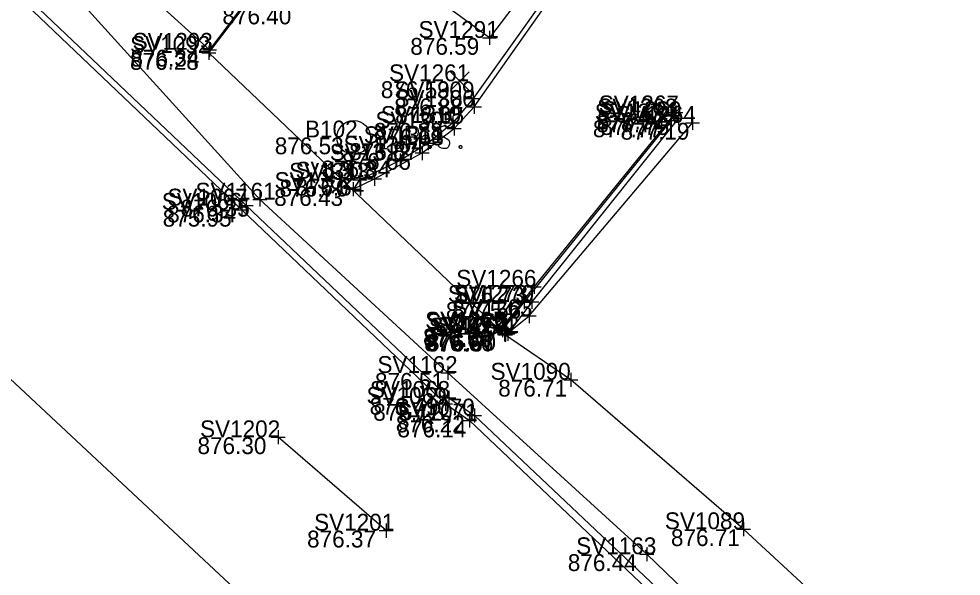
# Model space of a CAD drawing. Extents: x 1480001 to 1480402, y 379235 to 379603.
# Drawn here: x 1480268.3 to 1480335.4, y 379321.1 to 379360.8 of the extents above; entities that cross this region are included whole.
import ezdxf

# ---------------------------------------------------------------- set-up
doc = ezdxf.new("R2010")
doc.units = 0
for name, color, linetype in [('PM_P_CL_Double_Solid', 7, 'Continuous'), ('PM_X_Lane_Line', 7, 'Continuous'), ('PV_X_Curb', 7, 'Continuous'), ('PV_X_Driveway', 7, 'Continuous'), ('PV_X_Walk', 7, 'Continuous'), ('RD_X_Wall', 7, 'Continuous'), ('SV_P_Mon_Cells_Set', 7, 'Continuous'), ('SV_X_Random_Point', 7, 'Continuous'), ('SV_X_Shot_Marker', 7, 'Continuous'), ('SV_X_Text_Elevation', 7, 'Continuous'), ('SV_X_Text_Name', 7, 'Continuous'), ('UT_X_Water', 7, 'Continuous')]:
    doc.layers.add(name, color=color, linetype=linetype)

msp = doc.modelspace()

# ---------------------------------------------------------------- linework, layer by layer
at = {"layer": 'PM_P_CL_Double_Solid'}
msp.add_lwpolyline([(1480349.171, 379259.048), (1480326.954, 379280.06), (1480305.568, 379299.916), (1480284.393, 379319.578), (1480263.301, 379339.268), (1480242.575, 379359.213), (1480224.612, 379376.165), (1480208.191, 379391.527)], dxfattribs=at)
at = {"layer": 'PM_X_Lane_Line'}
msp.add_line((1480294.465, 379324.383), (1480286.766, 379331.035), dxfattribs=at)
at = {"layer": 'PV_X_Curb'}
for points in [[(1480221.495, 379406.235), (1480232.955, 379395.538), (1480249.633, 379380.044), (1480261.648, 379368.645), (1480263.97, 379366.423), (1480266.337, 379364.241), (1480284.168, 379347.237), (1480298.679, 379333.414), (1480300.396, 379332.229), (1480315.326, 379318.045), (1480323.87, 379309.98), (1480343.087, 379291.663), (1480360.248, 379275.585)], [(1480221.908, 379406.565), (1480233.156, 379396.15), (1480249.934, 379380.311), (1480262.014, 379368.886), (1480262.346, 379369.254), (1480264.513, 379367.165), (1480266.627, 379365.06), (1480266.41, 379364.736), (1480284.493, 379347.537), (1480298.919, 379333.838), (1480300.736, 379332.585), (1480315.855, 379318.308), (1480323.784, 379310.749), (1480324.548, 379310.084), (1480343.241, 379292.305), (1480360.288, 379276.242)], [(1480305.96, 379362.631), (1480300.661, 379355.172), (1480299.212, 379353.42), (1480297.448, 379351.979), (1480295.46, 379350.738), (1480292.571, 379349.379)]]:
    msp.add_lwpolyline(points, dxfattribs=at)
at = {"layer": 'PV_X_Driveway'}
for points in [[(1480292.11, 379348.712), (1480293.619, 379349.452), (1480297.028, 379351.282), (1480299.308, 379353.024), (1480300.735, 379354.566), (1480306.287, 379362.479)], [(1480302.714, 379338.771), (1480305.004, 379341.756), (1480315.073, 379354.175)], [(1480302.964, 379338.339), (1480304.645, 379339.672), (1480316.266, 379353.432)]]:
    msp.add_lwpolyline(points, dxfattribs=at)
at = {"layer": 'PV_X_Walk'}
for points in [[(1480355.123, 379297.828), (1480351.285, 379293.6), (1480334.098, 379309.328), (1480328.212, 379315.428), (1480328.737, 379316.329), (1480319.905, 379324.485), (1480307.606, 379335.13), (1480302.895, 379338.359), (1480281.823, 379358.406), (1480285.611, 379363.387), (1480280.441, 379367.109), (1480277.224, 379362.834), (1480260.819, 379378.019), (1480244.572, 379393.153), (1480235.613, 379401.335), (1480215.341, 379421.047)], [(1480304.825, 379363.469), (1480301.807, 379359.476), (1480289.404, 379368.611), (1480281.88, 379358.636), (1480277.384, 379362.714), (1480284.099, 379372.064), (1480266.845, 379384.676), (1480270.146, 379389.834)]]:
    msp.add_lwpolyline(points, dxfattribs=at)
at = {"layer": 'RD_X_Wall'}
msp.add_lwpolyline([(1480314.978, 379353.953), (1480315.27, 379353.766), (1480304.822, 379340.687), (1480303.116, 379338.406), (1480302.744, 379338.663), (1480304.288, 379340.662), (1480314.743, 379353.603)], dxfattribs=at)
at = {"layer": 'SV_P_Mon_Cells_Set'}
for points in [[(1480294.165, 379353.191), (1480294.518, 379353.191)], [(1480294.341, 379351.591), (1480294.341, 379353.191)], [(1480295.907, 379351.591), (1480295.907, 379353.191), (1480296.436, 379353.191), (1480296.491, 379353.178), (1480296.568, 379353.153), (1480296.601, 379353.128), (1480296.634, 379353.102), (1480296.678, 379353.04), (1480296.711, 379352.976), (1480296.733, 379352.876), (1480296.733, 379352.724), (1480296.722, 379352.674), (1480296.7, 379352.598), (1480296.656, 379352.51), (1480296.612, 379352.473), (1480296.579, 379352.447), (1480296.524, 379352.422), (1480296.436, 379352.41), (1480295.907, 379352.41)], [(1480298.916, 379353.077), (1480298.894, 379353.102), (1480298.861, 379353.128), (1480298.762, 379353.165), (1480298.64, 379353.191), (1480298.552, 379353.191), (1480298.519, 379353.191), (1480298.376, 379353.153), (1480298.255, 379353.077), (1480298.177, 379352.976), (1480298.155, 379352.876), (1480298.155, 379352.8), (1480298.177, 379352.699), (1480298.266, 379352.611), (1480298.872, 379352.233), (1480298.927, 379352.183), (1480298.949, 379352.132), (1480298.971, 379352.057), (1480298.971, 379351.981), (1480298.96, 379351.906), (1480298.949, 379351.855), (1480298.927, 379351.792), (1480298.905, 379351.742), (1480298.883, 379351.704), (1480298.85, 379351.666), (1480298.817, 379351.641), (1480298.773, 379351.616), (1480298.74, 379351.603), (1480298.64, 379351.591), (1480298.486, 379351.591), (1480298.387, 379351.616), (1480298.243, 379351.704), (1480298.155, 379351.78)], [(1480295.3, 379351.805), (1480295.355, 379351.805), (1480295.389, 379351.78), (1480295.422, 379351.729), (1480295.422, 379351.666), (1480295.389, 379351.616), (1480295.355, 379351.591), (1480295.3, 379351.591), (1480295.267, 379351.616), (1480295.234, 379351.666), (1480295.234, 379351.729), (1480295.267, 379351.78), (1480295.3, 379351.805)], [(1480297.549, 379351.805), (1480297.604, 379351.805), (1480297.637, 379351.78), (1480297.67, 379351.729), (1480297.67, 379351.666), (1480297.637, 379351.616), (1480297.604, 379351.591), (1480297.549, 379351.591), (1480297.516, 379351.616), (1480297.483, 379351.666), (1480297.483, 379351.729), (1480297.516, 379351.78), (1480297.549, 379351.805)], [(1480299.732, 379351.805), (1480299.787, 379351.805), (1480299.82, 379351.78), (1480299.853, 379351.729), (1480299.853, 379351.666), (1480299.82, 379351.616), (1480299.787, 379351.591), (1480299.732, 379351.591), (1480299.698, 379351.616), (1480299.666, 379351.666), (1480299.666, 379351.729), (1480299.698, 379351.78), (1480299.732, 379351.805)], [(1480294.165, 379351.591), (1480294.518, 379351.591)]]:
    msp.add_lwpolyline(points, dxfattribs=at)
msp.add_circle((1480292.146, 379352.389), 1.2, dxfattribs=at)
at = {"layer": 'SV_X_Random_Point'}
for p, q in [((1480299.039, 379355.724), (1480300.373, 379357.059)), ((1480299.039, 379357.059), (1480300.373, 379355.724))]:
    msp.add_line(p, q, dxfattribs=at)
at = {"layer": 'SV_X_Shot_Marker'}
for p, q in [((1480301.807, 379359.976), (1480301.807, 379358.976)), ((1480281.88, 379359.136), (1480281.88, 379358.136)), ((1480301.307, 379359.476), (1480302.307, 379359.476)), ((1480301.807, 379359.476), (1480301.807, 379359.476)), ((1480281.38, 379358.636), (1480282.38, 379358.636)), ((1480281.823, 379358.906), (1480281.823, 379357.906)), ((1480281.88, 379358.636), (1480281.88, 379358.636)), ((1480281.323, 379358.406), (1480282.323, 379358.406)), ((1480281.823, 379358.406), (1480281.823, 379358.406)), ((1480300.161, 379355.172), (1480301.161, 379355.172)), ((1480300.661, 379355.672), (1480300.661, 379354.672)), ((1480300.661, 379355.172), (1480300.661, 379355.172)), ((1480300.235, 379354.566), (1480301.235, 379354.566)), ((1480300.735, 379355.066), (1480300.735, 379354.066)), ((1480300.735, 379354.566), (1480300.735, 379354.566)), ((1480314.978, 379354.453), (1480314.978, 379353.453)), ((1480315.073, 379354.675), (1480315.073, 379353.675)), ((1480299.212, 379353.92), (1480299.212, 379352.92)), ((1480314.478, 379353.953), (1480315.478, 379353.953)), ((1480314.573, 379354.175), (1480315.573, 379354.175)), ((1480314.743, 379354.103), (1480314.743, 379353.103)), ((1480314.77, 379353.766), (1480315.77, 379353.766)), ((1480314.978, 379353.953), (1480314.978, 379353.953)), ((1480315.073, 379354.175), (1480315.073, 379354.175)), ((1480315.27, 379354.266), (1480315.27, 379353.266)), ((1480315.27, 379353.766), (1480315.27, 379353.766)), ((1480316.266, 379353.932), (1480316.266, 379352.932)), ((1480298.712, 379353.42), (1480299.712, 379353.42)), ((1480299.212, 379353.42), (1480299.212, 379353.42)), ((1480299.308, 379353.524), (1480299.308, 379352.524)), ((1480314.243, 379353.603), (1480315.243, 379353.603)), ((1480314.743, 379353.603), (1480314.743, 379353.603)), ((1480315.766, 379353.432), (1480316.766, 379353.432)), ((1480316.266, 379353.432), (1480316.266, 379353.432)), ((1480297.448, 379352.479), (1480297.448, 379351.479)), ((1480298.808, 379353.024), (1480299.808, 379353.024)), ((1480299.308, 379353.024), (1480299.308, 379353.024)), ((1480296.948, 379351.979), (1480297.948, 379351.979)), ((1480297.028, 379351.782), (1480297.028, 379350.782)), ((1480297.448, 379351.979), (1480297.448, 379351.979)), ((1480295.46, 379351.238), (1480295.46, 379350.238)), ((1480296.528, 379351.282), (1480297.528, 379351.282)), ((1480297.028, 379351.282), (1480297.028, 379351.282)), ((1480294.96, 379350.738), (1480295.96, 379350.738)), ((1480295.46, 379350.738), (1480295.46, 379350.738)), ((1480292.571, 379349.879), (1480292.571, 379348.879)), ((1480293.619, 379349.952), (1480293.619, 379348.952)), ((1480292.071, 379349.379), (1480293.071, 379349.379)), ((1480292.11, 379349.212), (1480292.11, 379348.212)), ((1480292.571, 379349.379), (1480292.571, 379349.379)), ((1480293.119, 379349.452), (1480294.119, 379349.452)), ((1480293.619, 379349.452), (1480293.619, 379349.452)), ((1480285.468, 379348.459), (1480285.468, 379347.459)), ((1480291.61, 379348.712), (1480292.61, 379348.712)), ((1480292.11, 379348.712), (1480292.11, 379348.712)), ((1480284.168, 379347.737), (1480284.168, 379346.737)), ((1480284.493, 379348.037), (1480284.493, 379347.037)), ((1480284.968, 379347.959), (1480285.968, 379347.959)), ((1480285.468, 379347.959), (1480285.468, 379347.959)), ((1480283.668, 379347.237), (1480284.668, 379347.237)), ((1480283.993, 379347.537), (1480284.993, 379347.537)), ((1480284.168, 379347.237), (1480284.168, 379347.237)), ((1480284.493, 379347.537), (1480284.493, 379347.537)), ((1480304.504, 379341.756), (1480305.504, 379341.756)), ((1480305.004, 379342.256), (1480305.004, 379341.256)), ((1480305.004, 379341.756), (1480305.004, 379341.756)), ((1480304.288, 379341.162), (1480304.288, 379340.162)), ((1480304.822, 379341.187), (1480304.822, 379340.187)), ((1480303.788, 379340.662), (1480304.788, 379340.662)), ((1480304.288, 379340.662), (1480304.288, 379340.662)), ((1480304.322, 379340.687), (1480305.322, 379340.687)), ((1480304.822, 379340.687), (1480304.822, 379340.687)), ((1480304.145, 379339.672), (1480305.145, 379339.672)), ((1480304.645, 379340.172), (1480304.645, 379339.172)), ((1480304.645, 379339.672), (1480304.645, 379339.672)), ((1480302.714, 379339.271), (1480302.714, 379338.271)), ((1480302.744, 379339.163), (1480302.744, 379338.163)), ((1480302.214, 379338.771), (1480303.214, 379338.771)), ((1480302.244, 379338.663), (1480303.244, 379338.663)), ((1480302.395, 379338.359), (1480303.395, 379338.359)), ((1480302.464, 379338.339), (1480303.464, 379338.339)), ((1480302.616, 379338.406), (1480303.616, 379338.406)), ((1480302.714, 379338.771), (1480302.714, 379338.771)), ((1480302.744, 379338.663), (1480302.744, 379338.663)), ((1480302.895, 379338.859), (1480302.895, 379337.859)), ((1480302.895, 379338.359), (1480302.895, 379338.359)), ((1480302.964, 379338.839), (1480302.964, 379337.839)), ((1480302.964, 379338.339), (1480302.964, 379338.339)), ((1480303.116, 379338.906), (1480303.116, 379337.906)), ((1480303.116, 379338.406), (1480303.116, 379338.406)), ((1480298.848, 379336.114), (1480298.848, 379335.114)), ((1480307.606, 379335.63), (1480307.606, 379334.63)), ((1480298.348, 379335.614), (1480299.348, 379335.614)), ((1480298.848, 379335.614), (1480298.848, 379335.614)), ((1480307.106, 379335.13), (1480308.106, 379335.13)), ((1480307.606, 379335.13), (1480307.606, 379335.13)), ((1480298.919, 379334.338), (1480298.919, 379333.338)), ((1480298.419, 379333.838), (1480299.419, 379333.838)), ((1480298.679, 379333.914), (1480298.679, 379332.914)), ((1480298.919, 379333.838), (1480298.919, 379333.838)), ((1480298.179, 379333.414), (1480299.179, 379333.414)), ((1480298.679, 379333.414), (1480298.679, 379333.414)), ((1480300.736, 379333.085), (1480300.736, 379332.085)), ((1480300.236, 379332.585), (1480301.236, 379332.585)), ((1480300.396, 379332.729), (1480300.396, 379331.729)), ((1480300.736, 379332.585), (1480300.736, 379332.585)), ((1480299.896, 379332.229), (1480300.896, 379332.229)), ((1480300.396, 379332.229), (1480300.396, 379332.229)), ((1480286.266, 379331.035), (1480287.266, 379331.035)), ((1480286.766, 379331.535), (1480286.766, 379330.535)), ((1480286.766, 379331.035), (1480286.766, 379331.035)), ((1480319.905, 379324.985), (1480319.905, 379323.985)), ((1480293.965, 379324.383), (1480294.965, 379324.383)), ((1480294.465, 379324.883), (1480294.465, 379323.883)), ((1480294.465, 379324.383), (1480294.465, 379324.383)), ((1480319.405, 379324.485), (1480320.405, 379324.485)), ((1480319.905, 379324.485), (1480319.905, 379324.485)), ((1480313.013, 379323.205), (1480313.013, 379322.205)), ((1480312.513, 379322.705), (1480313.513, 379322.705)), ((1480313.013, 379322.705), (1480313.013, 379322.705))]:
    msp.add_line(p, q, dxfattribs=at)
at = {"layer": 'UT_X_Water'}
msp.add_lwpolyline([(1480212.628, 379415.684), (1480231.592, 379398.237), (1480249.493, 379381.828), (1480253.44, 379378.963), (1480259.284, 379374.539), (1480264.171, 379372.865), (1480269.434, 379369.248), (1480270.598, 379368.157), (1480270.755, 379365.904), (1480271.186, 379363.733), (1480285.468, 379347.959), (1480298.848, 379335.614), (1480313.013, 379322.705), (1480330.745, 379305.601), (1480344.344, 379292.312), (1480351.783, 379285.136)], dxfattribs=at)

# ---------------------------------------------------------------- texts
at = {"layer": 'SV_X_Text_Elevation'}
for s, p in [('876.40', (1480282.796, 379360.446)), ('876.59', (1480296.176, 379358.276)), ('876.34', (1480276.249, 379357.436)), ('876.28', (1480276.211, 379357.206)), ('876.59', (1480294.075, 379355.191)), ('876.88', (1480295.03, 379353.972)), ('876.65', (1480295.094, 379353.366)), ('877.74', (1480309.422, 379352.753)), ('876.82', (1480309.461, 379352.975)), ('877.75', (1480309.705, 379352.566)), ('876.88', (1480293.581, 379352.22)), ('877.77', (1480309.178, 379352.403)), ('877.19', (1480311.146, 379352.232)), ('876.53', (1480286.524, 379351.189)), ('876.68', (1480293.658, 379351.824)), ('876.87', (1480291.826, 379350.779)), ('876.66', (1480291.312, 379350.082)), ('876.84', (1480289.848, 379349.538)), ('876.70', (1480286.864, 379348.179)), ('876.64', (1480287.988, 379348.252)), ('876.43', (1480286.479, 379347.512)), ('876.35', (1480279.827, 379346.759)), ('875.95', (1480278.546, 379346.037)), ('876.34', (1480278.862, 379346.337)), ('876.73', (1480299.401, 379340.556)), ('877.54', (1480298.714, 379339.462)), ('877.56', (1480299.163, 379339.487)), ('876.92', (1480299.014, 379338.472)), ('876.64', (1480297.083, 379337.571)), ('876.89', (1480297.113, 379337.463)), ('876.66', (1480297.179, 379337.159)), ('876.67', (1480297.323, 379337.139)), ('876.90', (1480297.371, 379337.206)), ('876.51', (1480293.66, 379334.414)), ('876.71', (1480302.437, 379333.93)), ('876.49', (1480293.278, 379332.638)), ('876.12', (1480293.54, 379332.214)), ('876.22', (1480295.143, 379331.385)), ('876.14', (1480295.257, 379331.029)), ('876.30', (1480281.021, 379329.835)), ('876.37', (1480288.824, 379323.183)), ('876.71', (1480314.736, 379323.285)), ('876.44', (1480307.391, 379321.505))]:
    msp.add_text(s, height=1.2, dxfattribs=at).set_placement(p)
at = {"layer": 'SV_X_Text_Name'}
for s, p in [('SV1291', (1480296.762, 379359.476)), ('SV1293', (1480276.401, 379358.636)), ('SV1092', (1480276.221, 379358.406)), ('SV1261', (1480294.661, 379356.391)), ('SV1309', (1480295.04, 379355.172)), ('SV1306', (1480295.048, 379354.566)), ('SV1268', (1480309.489, 379353.953)), ('SV1267', (1480309.594, 379354.175)), ('SV1310', (1480294.083, 379353.42)), ('SV1274', (1480309.311, 379353.603)), ('SV1269', (1480309.781, 379353.766)), ('SV1264', (1480310.796, 379353.432)), ('SV1305', (1480293.696, 379353.024)), ('B102', (1480288.679, 379352.389)), ('SV1311', (1480292.857, 379351.979)), ('SV1304', (1480291.426, 379351.282)), ('SV1312', (1480290.444, 379350.738)), ('SV1313', (1480287.546, 379349.379)), ('SV1303', (1480288.007, 379349.452)), ('SV1302', (1480286.508, 379348.712)), ('SV1161', (1480280.877, 379347.959)), ('SV1066', (1480278.481, 379347.237)), ('SV1067', (1480278.881, 379347.537)), ('SV1266', (1480299.449, 379341.756)), ('SV1273', (1480298.847, 379340.662)), ('SV1270', (1480299.277, 379340.687)), ('SV1263', (1480299.166, 379339.672)), ('SV1265', (1480297.235, 379338.771)), ('SV1272', (1480297.312, 379338.663)), ('SV1262', (1480297.494, 379338.339)), ('SV1091', (1480297.717, 379338.359)), ('SV1271', (1480298.108, 379338.406)), ('SV1162', (1480293.832, 379335.614)), ('SV1090', (1480301.89, 379335.13)), ('SV1068', (1480293.298, 379333.838)), ('SV1069', (1480293.058, 379333.414)), ('SV1070', (1480295.058, 379332.585)), ('SV1071', (1480295.256, 379332.229)), ('SV1202', (1480281.202, 379331.035)), ('SV1201', (1480289.325, 379324.383)), ('SV1089', (1480314.303, 379324.485)), ('SV1163', (1480307.988, 379322.705))]:
    msp.add_text(s, height=1.2, dxfattribs=at).set_placement(p)

doc.saveas('drawing.dxf')
